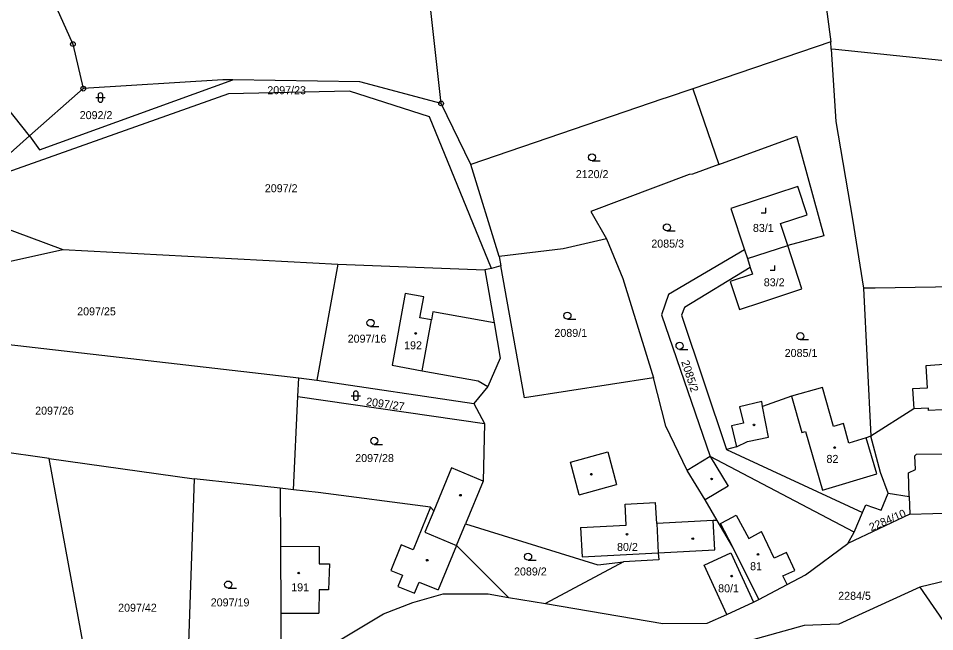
# Model space of a CAD drawing. Extents: x -725728 to -720881, y -1068679 to -1063504.
# Drawn here: x -722064.8 to -721870.1, y -1066607 to -1066476.7 of the extents above; entities that cross this region are included whole.
import ezdxf

# ---------------------------------------------------------------- set-up
doc = ezdxf.new("R2010")
doc.units = 0
for name, color, linetype in [('Hranice parcel', 7, 'Continuous'), ('Parcelní čísla', 7, 'Continuous'), ('Vnitřní kresba', 7, 'Continuous'), ('Značky bodu BP', 7, 'Continuous'), ('Značky budov', 7, 'Continuous'), ('Značky kultur', 7, 'Continuous')]:
    doc.layers.add(name, color=color, linetype=linetype)

msp = doc.modelspace()

# ---------------------------------------------------------------- linework, layer by layer
at = {"layer": 'Hranice parcel'}
for p, q in [((-721892.2, -1066481.66), (-721921.55, -1066491.67)), ((-721892.1, -1066483.26), (-721892.2, -1066481.66)), ((-722062.45, -1066501.69), (-722078.36, -1066481.8)), ((-722051.04, -1066491.64), (-722062.45, -1066501.69)), ((-721921.55, -1066491.67), (-721915.98, -1066507.73)), ((-721968.71, -1066507.75), (-721975, -1066494.79)), ((-722073.94, -1066511.81), (-722062.45, -1066501.69)), ((-721962.66, -1066527.31), (-721968.71, -1066507.75)), ((-722079.61, -1066516.8), (-722055.38, -1066525.85)), ((-722055.38, -1066525.85), (-721996.95, -1066528.96)), ((-721910.56, -1066525.87), (-721909.94, -1066527.75)), ((-721909.94, -1066527.75), (-721901.36, -1066524.99)), ((-721962.66, -1066527.31), (-721962.3, -1066529.32)), ((-721909.94, -1066527.75), (-721909.33, -1066529.62)), ((-721996.95, -1066528.96), (-722001.4, -1066553.59)), ((-721996.95, -1066528.96), (-721965.73, -1066530.17)), ((-721964.32, -1066529.82), (-721965.73, -1066530.17)), ((-721965.73, -1066530.17), (-721963.76, -1066541.43)), ((-721962.3, -1066529.32), (-721964.32, -1066529.82)), ((-721885.28, -1066534.01), (-721883.71, -1066565.51)), ((-722104.88, -1066541.6), (-722005.23, -1066553.1)), ((-722005.42, -1066557.04), (-722005.23, -1066553.1)), ((-722005.23, -1066553.1), (-722001.4, -1066553.59)), ((-722001.4, -1066553.59), (-721968.06, -1066558.54)), ((-721965.06, -1066554.92), (-721968.06, -1066558.54)), ((-722006.35, -1066576.88), (-722005.42, -1066557.04)), ((-722005.42, -1066557.04), (-721965.8, -1066562.79)), ((-721968.06, -1066558.54), (-721965.8, -1066562.79)), ((-722058.31, -1066570.2), (-722078.34, -1066567.37)), ((-721914.36, -1066568.28), (-721885.5, -1066581.68)), ((-722046.86, -1066632.49), (-722058.31, -1066570.2)), ((-722058.31, -1066570.2), (-722027.47, -1066574.55)), ((-721917.84, -1066569.81), (-721922.71, -1066572.77)), ((-721887.23, -1066585.86), (-721917.84, -1066569.81)), ((-722027.47, -1066574.55), (-722029.25, -1066624.93)), ((-722009.19, -1066576.56), (-722027.47, -1066574.55)), ((-722006.35, -1066576.88), (-722009.19, -1066576.56)), ((-721875.43, -1066582.08), (-721888.6, -1066588.29)), ((-721887.23, -1066585.86), (-721885.5, -1066581.68)), ((-721875.43, -1066582.08), (-721865.27, -1066581.79)), ((-721888.6, -1066588.29), (-721887.23, -1066585.86)), ((-721960.7, -1066599.73), (-721971.73, -1066588.7)), ((-721835.51, -1066588.41), (-721873.29, -1066597.58)), ((-721936.25, -1066592.17), (-721952.86, -1066601.06)), ((-721873.29, -1066597.58), (-721867.01, -1066606.72)), ((-721960.7, -1066599.73), (-721952.86, -1066601.06))]:
    msp.add_line(p, q, dxfattribs=at)
for points in [[(-721898.26, -1066355.61), (-721897.38, -1066425.95), (-721894.71, -1066462.94), (-721892.2, -1066481.66)], [(-721975, -1066494.79), (-721986.62, -1066390.04), (-722068.07, -1066391.45)], [(-722068.07, -1066391.45), (-722071.36, -1066432.18), (-722070.65, -1066443.54), (-722053.23, -1066482.18), (-722051.04, -1066491.64)], [(-721799.63, -1066493.27), (-721838.85, -1066488.84), (-721848.25, -1066487.78), (-721891.21, -1066483.35), (-721892.1, -1066483.26)], [(-721892.1, -1066483.26), (-721891.17, -1066498.64), (-721887.63, -1066519.37), (-721885.28, -1066534.01)], [(-722062.45, -1066501.69), (-722060.36, -1066504.66), (-722019.3, -1066489.8)], [(-722019.3, -1066489.8), (-722021.38, -1066489.77), (-722051.04, -1066491.64)], [(-721975, -1066494.79), (-721992.3, -1066490.17), (-722019.3, -1066489.8)], [(-721964.32, -1066529.82), (-721977.5, -1066497.63), (-721994.48, -1066492.16), (-722020.19, -1066492.74), (-722073.94, -1066511.81)], [(-721921.55, -1066491.67), (-721927.17, -1066493.59), (-721927.88, -1066493.83), (-721968.71, -1066507.75)], [(-721915.98, -1066507.73), (-721899.52, -1066501.7), (-721893.7, -1066522.89), (-721901.36, -1066524.99)], [(-721801.42, -1066509.16), (-721834.38, -1066505.32), (-721834.88, -1066513.45), (-721835.86, -1066513.5), (-721848.62, -1066514.13), (-721848.76, -1066532.94), (-721861.47, -1066533.68), (-721882.8, -1066534), (-721885.28, -1066534.01)], [(-721915.98, -1066507.73), (-721921.6, -1066509.8), (-721922.34, -1066509.88), (-721943.22, -1066517.72), (-721939.84, -1066523.56)], [(-721901.36, -1066524.99), (-721902.89, -1066520.31), (-721897.22, -1066518.46), (-721899.2, -1066512.41), (-721913.45, -1066517.09), (-721910.56, -1066525.87)], [(-722087.71, -1066523.92), (-722067.15, -1066528.44), (-722055.38, -1066525.85)], [(-721939.84, -1066523.56), (-721949.1, -1066525.69), (-721962.66, -1066527.31)], [(-721939.84, -1066523.56), (-721936.39, -1066532.01), (-721929.85, -1066553.09)], [(-721910.56, -1066525.87), (-721926.68, -1066535.39), (-721928.2, -1066539.67), (-721917.84, -1066569.81)], [(-721909.33, -1066529.62), (-721908.86, -1066531.05), (-721913.58, -1066532.6), (-721911.62, -1066538.54), (-721906.86, -1066536.98), (-721898.35, -1066534.2), (-721901.36, -1066524.99)], [(-721929.85, -1066553.09), (-721957.29, -1066557.31), (-721962.3, -1066529.32)], [(-721909.33, -1066529.62), (-721923.3, -1066538.13), (-721923.93, -1066539.76), (-721914.36, -1066568.28)], [(-721963.76, -1066541.43), (-721976.74, -1066539.08), (-721977.05, -1066540.75), (-721979.51, -1066540.3), (-721978.7, -1066535.87), (-721982.64, -1066535.16), (-721985.41, -1066550.41), (-721979.01, -1066551.57), (-721967.11, -1066553.73), (-721965.06, -1066554.92)], [(-721841.99, -1066573.97), (-721842.03, -1066572.49), (-721842.37, -1066560.81), (-721825.9, -1066557.54), (-721825.91, -1066558.18), (-721816.14, -1066558.4), (-721816.01, -1066552.48), (-721814.01, -1066552.6), (-721813.61, -1066538.69), (-721821.47, -1066538.46), (-721825.47, -1066538.35), (-721867.19, -1066550.15), (-721872, -1066550.52), (-721871.74, -1066555.27), (-721874.83, -1066555.44), (-721874.6, -1066559.7), (-721883.71, -1066565.51)], [(-721963.76, -1066541.43), (-721962.45, -1066548.89), (-721965.06, -1066554.92)], [(-721922.71, -1066572.77), (-721927.27, -1066563.38), (-721929.85, -1066553.09)], [(-721883.71, -1066565.51), (-721884.72, -1066565.85), (-721888.35, -1066566.95), (-721889.53, -1066562.81), (-721891.63, -1066563.41), (-721893.99, -1066555.13), (-721900.54, -1066557), (-721906.69, -1066559.16), (-721906.9, -1066558.08), (-721911.6, -1066559.22), (-721910.77, -1066562.7), (-721913.3, -1066563.3), (-721912.23, -1066567.77), (-721914.36, -1066568.28)], [(-721965.8, -1066562.79), (-721966.07, -1066575.02), (-721972.79, -1066572.24), (-721976.54, -1066581.31)], [(-721879.99, -1066577.62), (-721881.68, -1066573.23), (-721883.71, -1066565.51)], [(-721916.36, -1066583.38), (-721918.91, -1066579.03), (-721922.71, -1066572.77)], [(-722009.19, -1066576.56), (-722009.14, -1066588.88), (-722009.08, -1066603.06), (-722009.02, -1066616.25)], [(-721976.54, -1066581.31), (-721977.23, -1066580.58), (-722001.15, -1066577.45), (-722006.35, -1066576.88)], [(-721885.5, -1066581.68), (-721884.75, -1066580.09), (-721881.53, -1066581.17), (-721879.99, -1066577.62)], [(-721879.99, -1066577.62), (-721875.54, -1066578.28), (-721875.43, -1066582.08)], [(-721976.54, -1066581.31), (-721978.45, -1066585.91), (-721971.73, -1066588.7)], [(-721971.73, -1066588.7), (-721969.82, -1066584.1), (-721941.68, -1066592.82), (-721936.25, -1066592.17)], [(-721916.36, -1066583.38), (-721917.21, -1066583.42), (-721929.19, -1066584.05), (-721928.86, -1066590.29), (-721928.78, -1066591.73), (-721936.25, -1066592.17)], [(-721907.51, -1066600.21), (-721913.04, -1066589.03), (-721916.36, -1066583.38)], [(-721907.51, -1066600.21), (-721901.48, -1066597.01), (-721897.56, -1066594.93), (-721888.6, -1066588.29)], [(-721873.29, -1066597.58), (-721890.48, -1066605.44), (-721897.89, -1066605.71), (-721932.44, -1066615.37), (-721952.02, -1066613.77)], [(-722009.02, -1066616.25), (-721987.24, -1066603.24), (-721981.05, -1066600.85), (-721974.55, -1066599), (-721965, -1066599), (-721960.7, -1066599.73)], [(-721952.86, -1066601.06), (-721927.9, -1066605.3), (-721918.46, -1066605.19), (-721914.29, -1066603.36), (-721908.61, -1066600.72), (-721907.51, -1066600.21)]]:
    msp.add_lwpolyline(points, dxfattribs=at)
at = {"layer": 'Vnitřní kresba'}
for p, q in [((-721979.01, -1066551.57), (-721977.05, -1066540.75)), ((-721900.54, -1066557), (-721898.35, -1066564.69)), ((-721905.45, -1066565.66), (-721906.69, -1066559.16)), ((-721871.45, -1066559.53), (-721874.6, -1066559.7)), ((-721871.42, -1066560.06), (-721871.45, -1066559.53)), ((-721862.2, -1066559.56), (-721871.42, -1066560.06)), ((-721898.35, -1066564.69), (-721897.57, -1066564.47)), ((-721897.57, -1066564.47), (-721894.01, -1066576.94)), ((-721912.23, -1066567.77), (-721909.91, -1066566.63)), ((-721909.91, -1066566.63), (-721905.45, -1066565.66)), ((-721882.43, -1066573.45), (-721884.72, -1066565.85)), ((-721947.54, -1066571.01), (-721939.62, -1066568.84)), ((-721939.62, -1066568.84), (-721937.73, -1066575.75)), ((-721874.34, -1066569.64), (-721874, -1066569.33)), ((-721874, -1066569.33), (-721867.19, -1066569.23)), ((-721945.65, -1066577.92), (-721947.54, -1066571.01)), ((-721917.84, -1066569.81), (-721914.04, -1066576.07)), ((-721874.25, -1066572.54), (-721874.34, -1066569.64)), ((-721875.69, -1066573.28), (-721874.25, -1066572.54)), ((-721966.07, -1066575.02), (-721969.82, -1066584.1)), ((-721894.01, -1066576.94), (-721882.43, -1066573.45)), ((-721875.54, -1066578.28), (-721875.69, -1066573.28)), ((-721945.65, -1066577.92), (-721937.73, -1066575.75)), ((-721914.04, -1066576.07), (-721918.91, -1066579.03)), ((-721977.23, -1066580.58), (-721980.97, -1066589.62)), ((-721935.92, -1066579.9), (-721929.43, -1066579.56)), ((-721935.68, -1066584.39), (-721935.92, -1066579.9)), ((-721929.19, -1066584.05), (-721929.43, -1066579.56)), ((-721914.16, -1066583.26), (-721912.29, -1066582.26)), ((-721912.29, -1066582.26), (-721909.64, -1066587.22)), ((-721945.37, -1066584.9), (-721935.68, -1066584.39)), ((-721945.37, -1066584.9), (-721945.04, -1066591.14)), ((-721916.88, -1066589.66), (-721917.21, -1066583.42)), ((-721915.68, -1066584.07), (-721914.16, -1066583.26)), ((-721913.04, -1066589.03), (-721915.68, -1066584.07)), ((-721909.64, -1066587.22), (-721906.91, -1066585.76)), ((-721904.24, -1066591.42), (-721906.91, -1066585.76)), ((-721983.51, -1066588.57), (-721985.7, -1066593.99)), ((-721980.97, -1066589.62), (-721983.51, -1066588.57)), ((-721971.73, -1066588.7), (-721975.64, -1066598.15)), ((-722009.14, -1066588.88), (-722000.9, -1066588.9)), ((-722000.9, -1066588.9), (-722000.92, -1066592.62)), ((-721945.04, -1066591.14), (-721928.86, -1066590.29)), ((-721928.86, -1066590.29), (-721916.88, -1066589.66)), ((-721919.15, -1066592.9), (-721913.47, -1066590.26)), ((-721913.47, -1066590.26), (-721908.61, -1066600.72)), ((-721901.62, -1066590.18), (-721904.24, -1066591.42)), ((-721899.83, -1066593.99), (-721901.62, -1066590.18)), ((-722000.92, -1066592.62), (-721998.76, -1066592.63)), ((-721998.76, -1066592.63), (-721998.93, -1066598.16)), ((-721985.7, -1066593.99), (-721983.21, -1066595.02)), ((-721914.29, -1066603.36), (-721919.15, -1066592.9)), ((-721902.38, -1066595.19), (-721899.83, -1066593.99)), ((-721983.21, -1066595.02), (-721984.2, -1066597.42)), ((-721980.69, -1066598.87), (-721979.7, -1066596.47)), ((-721979.7, -1066596.47), (-721975.64, -1066598.15)), ((-721901.48, -1066597.01), (-721902.38, -1066595.19)), ((-722000.95, -1066598.15), (-722000.97, -1066603.08)), ((-721998.93, -1066598.16), (-722000.95, -1066598.15)), ((-721984.2, -1066597.42), (-721980.69, -1066598.87)), ((-722009.08, -1066603.06), (-722000.97, -1066603.08))]:
    msp.add_line(p, q, dxfattribs=at)
at = {"layer": 'Značky bodu BP'}
for centre, radius in [((-722053.23, -1066482.18), 0.5), ((-722053.23, -1066482.18), 0.0303), ((-722051.04, -1066491.64), 0.5), ((-722051.04, -1066491.64), 0.0303), ((-721975, -1066494.79), 0.5), ((-721975, -1066494.79), 0.0303)]:
    msp.add_circle(centre, radius, dxfattribs=at)
at = {"layer": 'Značky budov'}
for centre in [(-721980.41, -1066543.66), (-721908.53, -1066563.08), (-721891.38, -1066567.9), (-721943.08, -1066573.57), (-721917.53, -1066574.57), (-721970.9, -1066578.02), (-721935.51, -1066586.31), (-721921.53, -1066587.26), (-721907.68, -1066590.61), (-721977.97, -1066591.83), (-722005.26, -1066594.57), (-721913.27, -1066595.21)]:
    msp.add_circle(centre, 0.175, dxfattribs=at)
at = {"layer": 'Značky kultur'}
for p, q in [((-722047.89, -1066493.03), (-722047.89, -1066494.03)), ((-722046.89, -1066494.03), (-722046.89, -1066493.03)), ((-722048.39, -1066493.53), (-722046.39, -1066493.53)), ((-721942.95, -1066506.98), (-721941.2, -1066506.98)), ((-721907.02, -1066517.99), (-721906.02, -1066517.99)), ((-721906.02, -1066517.99), (-721906.02, -1066516.99)), ((-721927.04, -1066521.87), (-721925.29, -1066521.87)), ((-721905.07, -1066530.18), (-721904.07, -1066530.18)), ((-721904.07, -1066530.18), (-721904.07, -1066529.18)), ((-721948.17, -1066540.62), (-721946.42, -1066540.62)), ((-721990.01, -1066542.16), (-721988.26, -1066542.16)), ((-721898.69, -1066544.97), (-721896.94, -1066544.97)), ((-721924.35, -1066547.03), (-721922.6, -1066547.03)), ((-721994.13, -1066556.9), (-721992.13, -1066556.9)), ((-721993.63, -1066556.4), (-721993.63, -1066557.4)), ((-721992.63, -1066557.4), (-721992.63, -1066556.4)), ((-721989.21, -1066567.22), (-721987.46, -1066567.22)), ((-721956.53, -1066591.84), (-721954.78, -1066591.84)), ((-722020.25, -1066597.76), (-722018.5, -1066597.76))]:
    msp.add_line(p, q, dxfattribs=at)
for centre in [(-721942.95, -1066506.23), (-721927.04, -1066521.12), (-721948.17, -1066539.87), (-721990.01, -1066541.41), (-721898.69, -1066544.22), (-721924.35, -1066546.28), (-721989.21, -1066566.47), (-721956.53, -1066591.09), (-722020.25, -1066597.01)]:
    msp.add_circle(centre, 0.75, dxfattribs=at)
for centre, start, end in [((-722047.39, -1066493.03), 0, 180), ((-722047.39, -1066494.03), 180, 359.9879), ((-721993.13, -1066556.4), 0, 180), ((-721993.13, -1066557.4), 180, 359.9879)]:
    msp.add_arc(centre, 0.5, start, end, dxfattribs=at)

# ---------------------------------------------------------------- texts
at = {"layer": 'Parcelní čísla'}
for s, p in [('2097/23', (-722011.94, -1066492.82)), ('2092/2', (-722051.8, -1066498.11)), ('2120/2', (-721946.4, -1066510.65)), ('2097/2', (-722012.47, -1066513.65)), ('83/1', (-721908.76, -1066522.08)), ('2085/3', (-721930.35, -1066525.41)), ('83/2', (-721906.45, -1066533.63)), ('2097/25', (-722052.34, -1066539.81)), ('2097/16', (-721994.86, -1066545.61)), ('2089/1', (-721950.94, -1066544.39)), ('192', (-721982.87, -1066547.02)), ('2085/1', (-721902.01, -1066548.65)), ('2097/26', (-722061.27, -1066560.91)), ('2097/28', (-721993.26, -1066570.98)), ('82', (-721893.13, -1066571.16)), ('80/2', (-721937.63, -1066589.87)), ('81', (-721909.36, -1066593.96)), ('2089/2', (-721959.52, -1066595.08)), ('191', (-722006.86, -1066598.45)), ('80/1', (-721916.15, -1066598.66)), ('2284/5', (-721890.64, -1066600.25)), ('2097/19', (-722023.96, -1066601.65)), ('2097/42', (-722043.64, -1066602.78))]:
    msp.add_text(s, height=1.7, dxfattribs=at).set_placement(p)
for s, rotation, p in [('2085/2', 288, (-721924.01, -1066549.67)), ('2097/27', 352, (-721991.04, -1066558.91)), ('2284/10', 23, (-721883.63, -1066585.71))]:
    msp.add_text(s, height=1.7, rotation=rotation, dxfattribs=at).set_placement(p)

doc.saveas('drawing.dxf')
